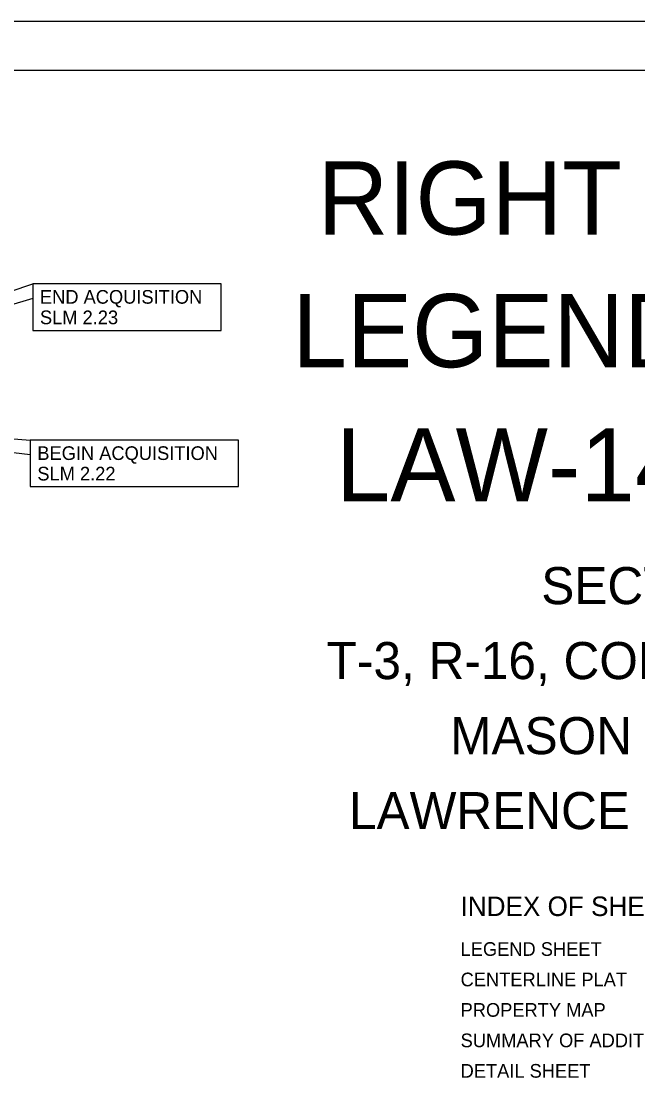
# Model space of a CAD drawing. Extents: x 0 to 34, y 0 to 22.
# Drawn here: x 9.19 to 15.51, y 11.04 to 22 of the extents above; entities that cross this region are included whole.
import ezdxf

# ---------------------------------------------------------------- set-up
doc = ezdxf.new("R2010")
doc.units = 0
for name, color, linetype in [('SH_Border', 7, 'Continuous'), ('SH_Cut_Line', 7, 'Continuous'), ('SH_Data', 7, 'Continuous'), ('SH_Text', 7, 'Continuous')]:
    doc.layers.add(name, color=color, linetype=linetype)

msp = doc.modelspace()

# ---------------------------------------------------------------- linework, layer by layer
at = {"layer": 'SH_Border'}
msp.add_lwpolyline([(1.5, 21.5), (33.5, 21.5), (33.5, 0.5), (1.5, 0.5)], close=True, dxfattribs=at)
at = {"layer": 'SH_Cut_Line'}
msp.add_lwpolyline([(0, 0), (34, 0), (34, 22), (0, 22)], close=True, dxfattribs=at)
at = {"layer": 'SH_Text'}
for points in [[(5.504, 18.028), (9.307, 19.311), (9.307, 19.161)], [(9.307, 18.834), (11.236, 18.834), (11.236, 19.311), (9.307, 19.311)], [(5.502, 18.014), (9.28, 17.711), (9.28, 17.561)], [(9.28, 17.234), (11.414, 17.234), (11.414, 17.711), (9.28, 17.711)]]:
    msp.add_lwpolyline(points, close=True, dxfattribs=at)

# ---------------------------------------------------------------- texts
at = {"layer": 'SH_Data'}
for s, height, p in [('RIGHT OF WAY', 0.75, (12.227, 19.816)), ('LEGEND SHEET', 0.75, (11.968, 18.457)), ('LAW-141-16.94', 0.75, (12.414, 17.082)), ('SECTION 19', 0.38, (14.519, 16.03)), ('T-3, R-16, CONGRESS LANDS', 0.38, (12.319, 15.262)), ('MASON TOWNSHIP', 0.38, (13.586, 14.493)), ('LAWRENCE COUNTY, OHIO', 0.38, (12.548, 13.725)), ('INDEX OF SHEETS:', 0.2, (13.692, 12.835)), ('LEGEND SHEET', 0.14, (13.692, 12.427)), ('CENTERLINE PLAT', 0.14, (13.692, 12.115)), ('PROPERTY MAP', 0.14, (13.692, 11.803)), ('SUMMARY OF ADDITIONAL R/W', 0.14, (13.692, 11.491)), ('DETAIL SHEET', 0.14, (13.692, 11.179))]:
    msp.add_text(s, height=height, dxfattribs=at).set_placement(p)
at = {"layer": 'SH_Text'}
for s, p in [('END ACQUISITION', (9.38, 19.108)), ('SLM 2.23', (9.38, 18.898)), ('BEGIN ACQUISITION', (9.353, 17.507)), ('SLM 2.22', (9.353, 17.297))]:
    msp.add_text(s, height=0.14, dxfattribs=at).set_placement(p)

doc.saveas('drawing.dxf')
